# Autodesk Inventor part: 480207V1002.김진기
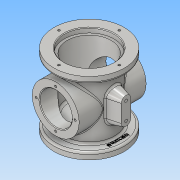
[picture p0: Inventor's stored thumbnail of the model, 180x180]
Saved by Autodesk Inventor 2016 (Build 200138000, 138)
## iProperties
Created: 2018-02
Part Number: 480207V1002.김진기
Material: 알루미늄 6061
Document SubType Name: Modeling
Designer: Administrator
Density: 2.7 g/cm^3
Appearance: 알루미늄 - 평지
Mass: 768.982 g
Surface Area: 820.894 cm^2
Volume: 284.808 cm^3
Author: Administrator
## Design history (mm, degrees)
sketch "스케치1"
  geometry: L1 (0, -54)-(0, 54); L2 (0, -54)-(-52.5, -54); L3 (-52.5, -54)-(-52.5, -44); L4 (-52.5, -44)-(-38, -44); L5 (-38, -44)-(-38, 44); L6 (-38, 44)-(-52.5, 44); L7 (-52.5, 44)-(-52.5, 54); L8 (-52.5, 54)-(0, 54); 2 further points
  constraints: 16 end point, 4 perpendicular, 2 point on line, 1 coincident, 1 horizontal, 1 midpoint, 1 parallel, 1 vertical, 1 vertical alignment
  dimensions: "d0" = 108 distance of L1.start L1.end; "d1" = 10 distance of L6.end L7.end; "d2" = 10 distance of L2.end L3.end; "d3" = 105 diameter of L7 L1; "d8" = 76 diameter of L5 L1
revolve "회전1" sketch "스케치1" stored, may be unused: angle "d5" = 90 deg
sketch "스케치3"
  geometry: L1 (-50, 0)-(50, 0); L2 (-50, 0)-(-50, 35); L3 (-50, 35)-(50, 35); L4 (50, 35)-(50, 0); 2 further points
  constraints: 8 end point, 2 perpendicular, 1 coincident, 1 horizontal, 1 midpoint, 1 vertical
  dimensions: "d9" = 100 distance of L1.start L1.end; "d10" = 70 diameter of L3 L1
revolve "회전2" sketch "스케치3" stored, may be unused: angle "d11" = 90 deg
sketch "스케치4"
  geometry: L1 (0, -32)-(0, 54); L2 (52.5, 54)-(-52.5, 54) reference; L3 (0, -32)-(-33, -32); L4 (-33, -32)-(-33, 47); L5 (-33, 47)-(-37, 47); L6 (-37, 47)-(-37, 54); L7 (-37, 54)-(0, 54); 1 further point
  constraints: 12 end point, 3 perpendicular, 2 point on line, 1 collinear, 1 horizontal, 1 midpoint, 1 vertical
  dimensions: "d22" = 74 diameter of L6 L1; "d23" = 66 diameter of L4 L1; "d24" = 7 distance between parallel lines of L2 L5; "d83" = 79 distance between parallel lines of L5 L3
revolve "회전3" sketch "스케치4" stored, may be unused: angle "d25" = 90 deg
hole "구멍2" diameter "d28" = 68; stored, may be unused: countersink angle "d32" = 90 deg, drill point angle "d34" = 0 deg; dims "d26" = 10, "d27" = 10, "d29" = 6, "d30" = 4, "d31" = 2, "d33" = 16
hole "구멍3" diameter "d37" = 10; stored, may be unused: countersink angle "d41" = 90 deg, drill point angle "d43" = 0 deg; dims "d35" = 10, "d36" = 10, "d38" = 6, "d39" = 4, "d40" = 2, "d42" = 16
hole "구멍4" diameter "d46" = 48; stored, may be unused: countersink angle "d50" = 90 deg, drill point angle "d52" = 0 deg; dims "d44" = 10, "d45" = 10, "d47" = 6, "d48" = 4, "d49" = 2, "d51" = 16
chamfer "모따기1" distance "d53" = 1; stored, may be unused: second distance "d54" = 2, angle "d55" = 45 deg
chamfer "모따기2" distance "d56" = 1; stored, may be unused: second distance "d57" = 2, angle "d58" = 45 deg
fillet "모깎기1" dims "d59" = 3
sketch "스케치5"
  geometry: 5 further points
  constraints: 2 horizontal alignment, 2 vertical alignment
  dimensions: "d60" = 45 distance of point (-45, 0) point (0, 0); "d61" = 45 distance of point (45, 0) point (0, 0); "d62" = 45 distance of point (0, 0) point (0, -45); "d63" = 45 distance of point (0, 45) point (0, 0)
hole "구멍5" sketch "스케치5" at (45, 0), (0, -45), (-45, 0), (0, 45) diameter "d64" = 3.242; stored, may be unused: countersink angle "d68" = 90 deg, drill point angle "d70" = 118 deg; dims "d65" = 4, "d66" = 4, "d67" = 2, "d69" = 6
fillet "모깎기2" dims "d71" = 3
sketch "스케치6"
  geometry: 5 further points
  constraints: 2 horizontal alignment, 2 vertical alignment
  dimensions: "d72" = 29 distance of point (-29, 0) point (0, 0); "d73" = 29 distance of point (29, 0) point (0, 0); "d74" = 29 distance of point (0, 29) point (0, 0); "d75" = 29 distance of point (0, -29) point (0, 0)
hole "구멍6" sketch "스케치6" at (0, 29), (29, 0), (0, -29), (-29, 0) diameter "d76" = 3.242; stored, may be unused: countersink angle "d80" = 90 deg, drill point angle "d82" = 118 deg; dims "d77" = 4, "d78" = 4, "d79" = 2, "d81" = 6
node "작업 평면2"
sketch "스케치7"
  geometry: L1 (-7, -13)-(-7, 13); L2 (7, -13)-(7, 13); A1 r 7 centre (0, 13) between (7, 13) and (-7, 13); A2 r 7 centre (0, -13) between (-7, -13) and (7, -13); 1 further point
  constraints: 4 end point, 4 point on circle, 3 tangent, 2 centre point, 2 vertical alignment, 1 parallel
  dimensions: "d85" = 7 radius of A1; "d86" = 7 radius of A2; "d88" = 13 distance of point (0, 0) A2.centre; "d89" = 13 distance of A1.centre point (0, 0)
extrude "돌출1" join sketch "스케치7" stored distance "d90" = 10; taper "d91" = 15 deg
fillet "모깎기3" dims "d92" = 3
hole "구멍7" diameter "d95" = 4.134; stored, may be unused: countersink angle "d99" = 90 deg, drill point angle "d101" = 118 deg; dims "d93" = 10, "d94" = 10, "d96" = 6, "d97" = 4, "d98" = 2, "d100" = 8
hole "구멍8" diameter "d104" = 4.134; stored, may be unused: countersink angle "d108" = 90 deg, drill point angle "d110" = 118 deg; dims "d102" = 10, "d103" = 10, "d105" = 6, "d106" = 4, "d107" = 2, "d109" = 8
sketch "스케치8"
  geometry: L1 (-15.909, -40.749)-(15.909, -40.749); L2 (15.909, -40.749)-(15.909, -45.251); L3 (15.909, -45.251)-(-15.909, -45.251); L4 (-15.909, -45.251)-(-15.909, -40.749); 4 further points
  constraints: 2 midpoint, 2 vertical alignment, 1 horizontal alignment, 2 other
  dimensions: "d111" = 43 distance of point (0, -43) point (0, 0); "d112" = 31.81848 distance of L2.end L3.end; "d113" = 4.50243 distance of L1.end L2.end; "d114" = 2.25122 vertical distance of point (15.909, -43) point (0, -45.251)
feature "엠보싱1" sketch "스케치8" dims "d22" = 74, "d23" = 66, "d24" = 7, "d83" = 79, "d115" = 0.5, "d116" = 0
node "솔리드1"
mirror "대칭1"
other parameters: "d84" = 55
